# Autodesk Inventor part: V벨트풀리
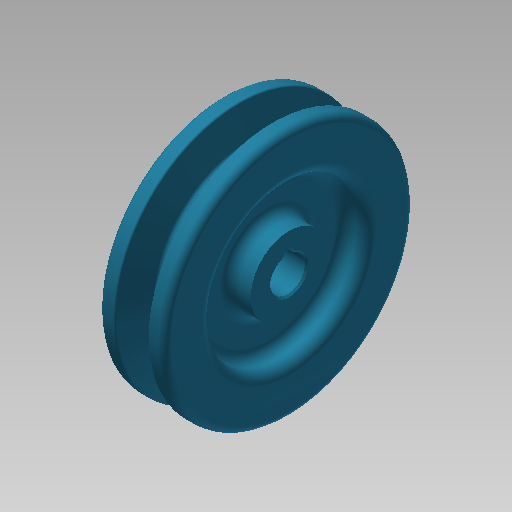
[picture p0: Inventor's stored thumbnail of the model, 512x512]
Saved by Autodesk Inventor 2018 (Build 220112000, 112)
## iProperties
Created: 2015-11
Part Number: V벨트풀리
Material: 강철, 탄소
Document SubType Name: Modeling
Designer: mduedu
Density: 7.87 g/cm^3
Mass: 380.065 g
Surface Area: 160.69 cm^2
Volume: 48.2929 cm^3
Appearance: 터키옥색
Author: mduedu
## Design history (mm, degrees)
sketch "스케치1"
  geometry: L1 (-9.5, 0)-(9.5, 0); L2 (0, 0)-(0, 35.7); L3 (-4.825, 35.7)-(-9.5, 35.7); L4 (-9.5, 35.7)-(-9.5, 0); L5 (0, 26.7)-(-2.074, 26.7); L6 (-2.074, 26.7)-(-4.825, 35.7); L7 (4.825, 35.7)-(9.5, 35.7); L8 (9.5, 35.7)-(9.5, 0); L9 (0, 26.7)-(2.074, 26.7); L10 (2.074, 26.7)-(4.825, 35.7); L11 (-9.5, 33)-(9.5, 33); 3 further points
  constraints: 22 end point, 7 point on line, 4 perpendicular, 3 symmetric about line, 1 coincident, 1 horizontal, 1 horizontal alignment, 1 midpoint, 1 vertical
  dimensions: "d0" = 19 distance of L1.start L1.end; "d2" = 71.4 diameter of L2.end L1 (derived); "d3" = 34 deg angle of L10 L6; "d4" = 6.3 distance between parallel lines of L11 L9; "d5" = 2.7 distance between parallel lines of L7 L11; "d6" = 8 distance of point (4, 33) point (-4, 33); "d7" = 66 diameter of L11 L1
revolve "회전1" sketch "스케치1" stored, may be unused: angle "d8" = 90 deg
sketch "스케치2"
  geometry: C1 r 22 at (0, 0); C2 r 11 at (0, 0); 1 further point
  constraints: 2 centre point, 2 coincident
  dimensions: "d9" = 44 diameter of C1; "d10" = 22 diameter of C2
extrude "돌출1" cut sketch "스케치2" distance "d11" = 6; taper "d12" = 0 deg
fillet "모깎기1" dims "d13" = 3
fillet "모깎기2" dims "d14" = 3
fillet "모깎기3" dims "d15" = 1, "d16" = 0.5, "d17" = 2
hole "구멍1" diameter "d20" = 10; stored, may be unused: countersink angle "d24" = 90 deg, drill point angle "d26" = 118 deg; dims "d18" = 10, "d19" = 10, "d21" = 6, "d22" = 4, "d23" = 2, "d25" = 8
sketch "스케치3"
  geometry: L1 (-1.5, 0)-(1.5, 0); L2 (1.5, 0)-(1.5, 6.4); L3 (1.5, 6.4)-(-1.5, 6.4); L4 (-1.5, 6.4)-(-1.5, 0); 2 further points
  constraints: 8 end point, 2 parallel, 1 coincident, 1 horizontal, 1 midpoint, 1 perpendicular
  dimensions: "d27" = 3 distance of L2.end L3.end; "d29" = 6.4 distance of L3.end L1.start
extrude "돌출2" cut sketch "스케치3" extent not by distance; stored distance "d30" = 6; taper "d31" = 0 deg
chamfer "모따기1" distance "d32" = 0.5; stored, may be unused: second distance "d33" = 2, angle "d34" = 45 deg
node "솔리드1"
mirror "대칭1"
